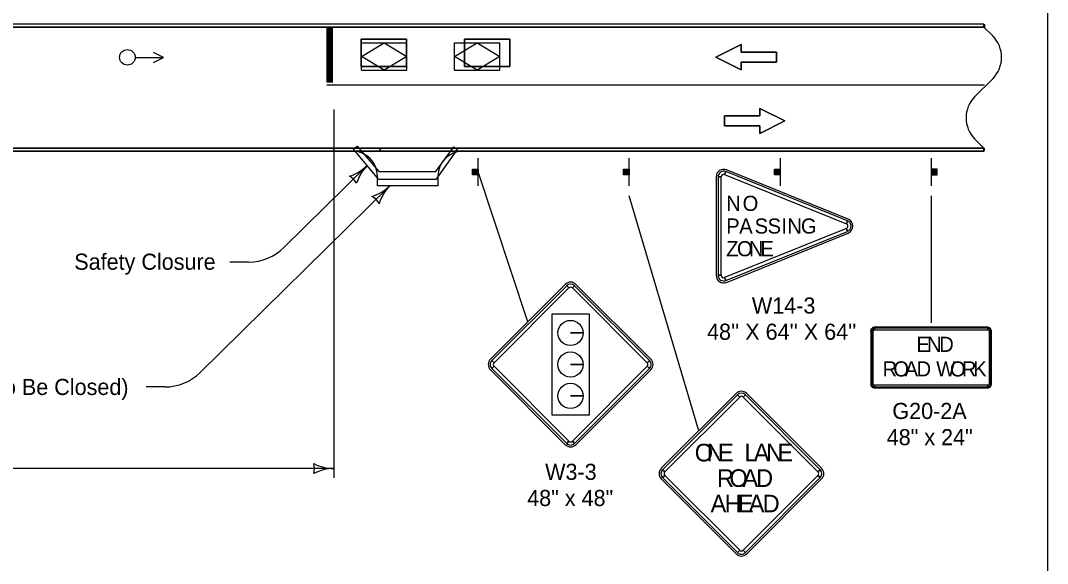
# Model space of a CAD drawing. Extents: x -2134934 to -2119606, y -2139046 to -2137036.
# Drawn here: x -2128116 to -2127097, y -2138077 to -2137539 of the extents above; entities that cross this region are included whole.
import ezdxf

# ---------------------------------------------------------------- set-up
doc = ezdxf.new("R2010")
doc.units = 0
for name, color, linetype in [('Default', 7, 'Continuous'), ('dsnCellElements', 7, 'Continuous'), ('dsnStdLabel', 7, 'Continuous'), ('dsnStdLineWork', 7, 'Continuous'), ('Level 2', 7, 'Continuous'), ('Level 4', 7, 'Continuous')]:
    doc.layers.add(name, color=color, linetype=linetype)

msp = doc.modelspace()

# ---------------------------------------------------------------- linework, layer by layer
at = {"layer": 'Default'}
for p, q in [((-2127785.6, -2137666.4), (-2127781.9, -2137663.4)), ((-2127760.4, -2137696.5), (-2127785.6, -2137666.4)), ((-2127781.9, -2137663.4), (-2127760.4, -2137688.4)), ((-2127704, -2137688.4), (-2127686.2, -2137664.1)), ((-2127682.7, -2137666.7), (-2127704, -2137696.5)), ((-2127686.2, -2137664.1), (-2127682.7, -2137666.7)), ((-2127760.4, -2137688.4), (-2127704, -2137688.4)), ((-2127704, -2137696.5), (-2127760.4, -2137696.5))]:
    msp.add_line(p, q, dxfattribs=at)
msp.add_lwpolyline([(-2130232, -2137035.9), (-2127097, -2137035.9), (-2127097, -2139045.9), (-2130232, -2139045.9)], close=True, dxfattribs=at)
at = {"layer": 'dsnCellElements'}
for centre, radius, start, end in [((-2127802.3, -2137652.6), 42.5, 287.1972, 315.2696), ((-2127741.9, -2137712.4), 42.5, 135.2696, 163.3421), ((-2127797.2, -2137707.8), 16.4, 27.5363, 63.003), ((-2127779.9, -2137672.7), 42.5, 287.1972, 315.2696), ((-2127719.5, -2137732.6), 42.5, 135.2696, 163.3421), ((-2127774.8, -2137728), 16.4, 27.5363, 63.003), ((-2127840.8, -2137983.3), 16.4, 342.2666, 17.7334), ((-2127805.1, -2137940.8), 42.5, 241.9275, 270), ((-2127805.1, -2138025.8), 42.5, 90, 118.0725)]:
    msp.add_arc(centre, radius, start, end, dxfattribs=at)
at = {"layer": 'dsnStdLabel'}
for p, q in [((-2127425.8, -2137693.8), (-2127425.8, -2137791.5)), ((-2127423.9, -2137693.8), (-2127420.8, -2137693.8)), ((-2127417.4, -2137691.5), (-2127416.2, -2137688.6)), ((-2127294.7, -2137735.7), (-2127415.5, -2137686.8)), ((-2127295.4, -2137737.4), (-2127296.5, -2137740.3)), ((-2127415.5, -2137798.5), (-2127294.7, -2137749.6)), ((-2127296.5, -2137745), (-2127295.4, -2137747.9)), ((-2127420.8, -2137791.5), (-2127423.9, -2137791.5)), ((-2127416.2, -2137796.7), (-2127417.4, -2137793.8)), ((-2127575.5, -2137800.5), (-2127649.7, -2137874.7)), ((-2127574.1, -2137801.8), (-2127571.9, -2137804)), ((-2127568.4, -2137804), (-2127566.2, -2137801.8)), ((-2127490.6, -2137874.7), (-2127564.9, -2137800.5)), ((-2127156.2, -2137843.1), (-2127268.7, -2137843.1)), ((-2127268.7, -2137845.6), (-2127268.7, -2137844.1)), ((-2127156.2, -2137844.1), (-2127156.2, -2137845.6)), ((-2127557.8, -2137848.7), (-2127570.3, -2137848.7)), ((-2127570.3, -2137848.7), (-2127557.8, -2137848.7)), ((-2127272.4, -2137846.9), (-2127272.4, -2137899.4)), ((-2127271.5, -2137846.9), (-2127269.9, -2137846.9)), ((-2127154.9, -2137846.9), (-2127153.4, -2137846.9)), ((-2127152.4, -2137899.4), (-2127152.4, -2137846.9)), ((-2127646.2, -2137878.3), (-2127648.4, -2137876.1)), ((-2127491.9, -2137876.1), (-2127494.1, -2137878.3)), ((-2127649.7, -2137885.4), (-2127575.5, -2137959.6)), ((-2127648.4, -2137884), (-2127646.2, -2137881.8)), ((-2127557.8, -2137880), (-2127570.3, -2137880)), ((-2127570.3, -2137880), (-2127557.8, -2137880)), ((-2127564.9, -2137959.6), (-2127490.6, -2137885.4)), ((-2127494.1, -2137881.8), (-2127491.9, -2137884)), ((-2127269.9, -2137899.4), (-2127271.5, -2137899.4)), ((-2127268.7, -2137902.2), (-2127268.7, -2137900.6)), ((-2127268.7, -2137903.1), (-2127156.2, -2137903.1)), ((-2127156.2, -2137900.6), (-2127156.2, -2137902.2)), ((-2127153.4, -2137899.4), (-2127154.9, -2137899.4)), ((-2127557.8, -2137911.2), (-2127570.3, -2137911.2)), ((-2127570.3, -2137911.2), (-2127557.8, -2137911.2)), ((-2127406, -2137908.8), (-2127480.2, -2137983)), ((-2127404.7, -2137910.1), (-2127402.4, -2137912.3)), ((-2127398.9, -2137912.3), (-2127396.7, -2137910.1)), ((-2127321.1, -2137983), (-2127395.4, -2137908.8)), ((-2127571.9, -2137956.1), (-2127574.1, -2137958.3)), ((-2127566.2, -2137958.3), (-2127568.4, -2137956.1)), ((-2127476.7, -2137986.6), (-2127478.9, -2137984.4)), ((-2127322.5, -2137984.4), (-2127324.7, -2137986.6)), ((-2127480.2, -2137993.6), (-2127406, -2138067.9)), ((-2127478.9, -2137992.3), (-2127476.7, -2137990.1)), ((-2127395.4, -2138067.9), (-2127321.1, -2137993.6)), ((-2127324.7, -2137990.1), (-2127322.5, -2137992.3)), ((-2127402.4, -2138064.4), (-2127404.7, -2138066.6)), ((-2127396.7, -2138066.6), (-2127398.9, -2138064.4))]:
    msp.add_line(p, q, dxfattribs=at)
for points in [[(-2127423.9, -2137693.8), (-2127423.9, -2137791.5), (-2127420.8, -2137791.5), (-2127420.8, -2137693.8), (-2127423.9, -2137693.8)], [(-2127295.4, -2137737.4), (-2127416.2, -2137688.6), (-2127417.4, -2137691.5), (-2127296.5, -2137740.3), (-2127295.4, -2137737.4)], [(-2127416.2, -2137796.7), (-2127295.4, -2137747.9), (-2127296.5, -2137745), (-2127417.4, -2137793.8), (-2127416.2, -2137796.7)], [(-2127574.1, -2137801.8), (-2127648.4, -2137876.1), (-2127646.2, -2137878.3), (-2127571.9, -2137804), (-2127574.1, -2137801.8)], [(-2127491.9, -2137876.1), (-2127566.2, -2137801.8), (-2127568.4, -2137804), (-2127494.1, -2137878.3), (-2127491.9, -2137876.1)], [(-2127551.4, -2137830.1), (-2127588.9, -2137830.1), (-2127588.9, -2137930), (-2127551.4, -2137930), (-2127551.4, -2137830.1)], [(-2127156.2, -2137844.1), (-2127268.7, -2137844.1), (-2127268.7, -2137845.6), (-2127156.2, -2137845.6), (-2127156.2, -2137844.1)], [(-2127271.5, -2137846.9), (-2127271.5, -2137899.4), (-2127269.9, -2137899.4), (-2127269.9, -2137846.9), (-2127271.5, -2137846.9)], [(-2127153.4, -2137899.4), (-2127153.4, -2137846.9), (-2127154.9, -2137846.9), (-2127154.9, -2137899.4), (-2127153.4, -2137899.4)], [(-2127648.4, -2137884), (-2127574.1, -2137958.3), (-2127571.9, -2137956.1), (-2127646.2, -2137881.8), (-2127648.4, -2137884)], [(-2127566.2, -2137958.3), (-2127491.9, -2137884), (-2127494.1, -2137881.8), (-2127568.4, -2137956.1), (-2127566.2, -2137958.3)], [(-2127268.7, -2137902.2), (-2127156.2, -2137902.2), (-2127156.2, -2137900.6), (-2127268.7, -2137900.6), (-2127268.7, -2137902.2)], [(-2127404.7, -2137910.1), (-2127478.9, -2137984.4), (-2127476.7, -2137986.6), (-2127402.4, -2137912.3), (-2127404.7, -2137910.1)], [(-2127322.5, -2137984.4), (-2127396.7, -2137910.1), (-2127398.9, -2137912.3), (-2127324.7, -2137986.6), (-2127322.5, -2137984.4)], [(-2127478.9, -2137992.3), (-2127404.7, -2138066.6), (-2127402.4, -2138064.4), (-2127476.7, -2137990.1), (-2127478.9, -2137992.3)], [(-2127396.7, -2138066.6), (-2127322.5, -2137992.3), (-2127324.7, -2137990.1), (-2127398.9, -2138064.4), (-2127396.7, -2138066.6)]]:
    msp.add_lwpolyline(points, close=True, dxfattribs=at)
for centre in [(-2127570.3, -2137848.7), (-2127570.3, -2137880), (-2127570.3, -2137911.2)]:
    msp.add_circle(centre, 12.5, dxfattribs=at)
for centre, radius, start, end in [((-2127418.3, -2137693.8), 7.5, 67.9757, 179.9998), ((-2127418.3, -2137693.8), 5.62, 67.9757, 179.9998), ((-2127418.3, -2137693.8), 2.5, 67.9757, 179.9998), ((-2127297.5, -2137742.6), 2.5, 292.0246, 67.9754), ((-2127297.5, -2137742.6), 5.62, 292.0246, 67.9754), ((-2127297.5, -2137742.6), 7.5, 292.0246, 67.976), ((-2127418.3, -2137791.5), 7.5, 179.9998, 292.0246), ((-2127418.3, -2137791.5), 5.62, 179.9998, 292.0246), ((-2127418.3, -2137791.5), 2.5, 179.9998, 292.0246), ((-2127570.2, -2137805.8), 7.5, 45, 134.9997), ((-2127570.2, -2137805.8), 5.62, 45, 134.9997), ((-2127570.2, -2137805.8), 2.5, 45, 134.9997), ((-2127268.7, -2137846.9), 3.75, 90.0002, 179.9998), ((-2127268.7, -2137846.9), 2.81, 90.0002, 179.9998), ((-2127268.7, -2137846.9), 1.25, 90.0002, 179.9998), ((-2127156.2, -2137846.9), 3.75, 0, 90.0002), ((-2127156.2, -2137846.9), 2.81, 0, 90.0002), ((-2127156.2, -2137846.9), 1.25, 0, 90.0002), ((-2127644.4, -2137880), 7.5, 134.9997, 225), ((-2127644.4, -2137880), 5.62, 134.9997, 225), ((-2127495.9, -2137880), 5.62, 315.0002, 44.9998), ((-2127495.9, -2137880), 7.5, 315.0002, 44.9998), ((-2127644.4, -2137880), 2.5, 134.9997, 225), ((-2127495.9, -2137880), 2.5, 315.0002, 44.9998), ((-2127400.7, -2137914.1), 7.5, 45, 134.9997), ((-2127268.7, -2137899.4), 3.75, 179.9998, 270.0001), ((-2127268.7, -2137899.4), 2.81, 179.9998, 270.0001), ((-2127268.7, -2137899.4), 1.25, 179.9998, 270.0001), ((-2127156.2, -2137899.4), 3.75, 270.0001, 0.0003), ((-2127156.2, -2137899.4), 2.81, 270.0001, 0.0003), ((-2127156.2, -2137899.4), 1.25, 270.0001, 0.0003), ((-2127400.7, -2137914.1), 5.62, 45, 134.9997), ((-2127400.7, -2137914.1), 2.5, 45, 134.9997), ((-2127570.2, -2137954.3), 5.62, 225, 315.0002), ((-2127570.2, -2137954.3), 2.5, 225, 315.0002), ((-2127570.2, -2137954.3), 7.5, 225, 315.0002), ((-2127474.9, -2137988.3), 7.5, 134.9997, 225), ((-2127474.9, -2137988.3), 5.62, 134.9997, 225), ((-2127474.9, -2137988.3), 2.5, 134.9997, 225), ((-2127326.4, -2137988.3), 2.5, 315.0002, 44.9998), ((-2127326.4, -2137988.3), 5.62, 315.0002, 44.9998), ((-2127326.4, -2137988.3), 7.5, 315.0002, 44.9998), ((-2127400.7, -2138062.6), 7.5, 225, 315.0002), ((-2127400.7, -2138062.6), 5.62, 225, 315.0002), ((-2127400.7, -2138062.6), 2.5, 225, 315.0002)]:
    msp.add_arc(centre, radius, start, end, dxfattribs=at)
at = {"layer": 'dsnStdLineWork'}
for p, q in [((-2127160.1, -2137542.2), (-2128660.1, -2137542.2)), ((-2127160.1, -2137542.2), (-2128660.1, -2137542.2)), ((-2127160.1, -2137545.2), (-2128660.1, -2137545.2)), ((-2128660.1, -2137545.2), (-2127810.1, -2137545.2)), ((-2127808.1, -2137545.2), (-2127807.1, -2137545.2)), ((-2127807.1, -2137545.2), (-2127806.1, -2137545.2)), ((-2127806.1, -2137545.2), (-2127805.1, -2137545.2)), ((-2127805.1, -2137545.2), (-2127160.1, -2137545.2)), ((-2127160.1, -2137545.2), (-2127160.1, -2137542.2)), ((-2127159.5, -2137542.2), (-2127159.5, -2137545.2)), ((-2127159.5, -2137602.7), (-2127812, -2137602.7)), ((-2128660.1, -2137665.2), (-2127159.5, -2137665.2)), ((-2127805.1, -2137665.2), (-2128280.3, -2137665.2)), ((-2128278.1, -2137668.2), (-2127805.1, -2137668.2)), ((-2127805.1, -2137668.2), (-2127805.1, -2137665.2)), ((-2127805.1, -2137665.2), (-2127805.1, -2137668.2)), ((-2127758.7, -2137665.2), (-2127805.1, -2137665.2)), ((-2127805.1, -2137668.2), (-2127759.9, -2137668.2)), ((-2127759.9, -2137668.2), (-2127758.7, -2137665.2)), ((-2127758.7, -2137665.2), (-2127759.9, -2137668.2)), ((-2127759.9, -2137668.2), (-2127160.1, -2137668.2)), ((-2127160.1, -2137665.2), (-2127758.7, -2137665.2)), ((-2127160.1, -2137668.2), (-2127160.1, -2137665.2)), ((-2127159.5, -2137668.2), (-2127159.5, -2137665.2))]:
    msp.add_line(p, q, dxfattribs=at)
for points in [[(-2128471.3, -2137545.2), (-2127158.8, -2137545.2)], [(-2127810.1, -2137545.2), (-2127809.1, -2137545.2), (-2127808.1, -2137545.2)], [(-2127160.1, -2137665.2), (-2128470.1, -2137665.2)], [(-2127160.1, -2137668.2), (-2128470.1, -2137668.2)]]:
    msp.add_lwpolyline(points, dxfattribs=at)
at = {"layer": 'Level 2'}
for p, q in [((-2127160.1, -2137545.2), (-2128660.1, -2137545.2)), ((-2127812, -2137545.2), (-2127812, -2137600.2)), ((-2127811, -2137545.2), (-2127811, -2137600.2)), ((-2127810, -2137545.2), (-2127810, -2137600.2)), ((-2127809, -2137545.2), (-2127809, -2137600.2)), ((-2127808, -2137545.2), (-2127808, -2137600.2)), ((-2127807, -2137545.2), (-2127807, -2137600.2)), ((-2127160.1, -2137545.2), (-2127151.3, -2137553.9)), ((-2127151.3, -2137553.9), (-2127160.1, -2137545.2)), ((-2127778.1, -2137557.2), (-2127733.1, -2137557.2)), ((-2127778.1, -2137584.2), (-2127778.1, -2137557.2)), ((-2127733.1, -2137557.2), (-2127778.1, -2137557.2)), ((-2127778.1, -2137557.2), (-2127778.1, -2137584.2)), ((-2127777.8, -2137587.8), (-2127777.8, -2137560.8)), ((-2127777.8, -2137560.8), (-2127732.8, -2137560.8)), ((-2127733.1, -2137557.2), (-2127733.1, -2137584.2)), ((-2127733.1, -2137584.2), (-2127733.1, -2137557.2)), ((-2127732.8, -2137587.8), (-2127732.8, -2137560.8)), ((-2127685.6, -2137587.9), (-2127685.6, -2137560.9)), ((-2127685.6, -2137560.9), (-2127640.6, -2137560.9)), ((-2127675.4, -2137557.2), (-2127630.4, -2137557.2)), ((-2127675.4, -2137584.2), (-2127675.4, -2137557.2)), ((-2127630.4, -2137557.2), (-2127675.4, -2137557.2)), ((-2127675.4, -2137557.2), (-2127675.4, -2137584.2)), ((-2127640.6, -2137587.9), (-2127640.6, -2137560.9)), ((-2127630.4, -2137557.2), (-2127630.4, -2137584.2)), ((-2127630.4, -2137584.2), (-2127630.4, -2137557.2)), ((-2128002.4, -2137575.5), (-2127974.4, -2137575.5)), ((-2127733.1, -2137584.2), (-2127778.1, -2137584.2)), ((-2127778.1, -2137584.2), (-2127733.1, -2137584.2)), ((-2127777.8, -2137587.8), (-2127732.8, -2137587.8)), ((-2127685.6, -2137587.9), (-2127640.6, -2137587.9)), ((-2127630.4, -2137584.2), (-2127675.4, -2137584.2)), ((-2127675.4, -2137584.2), (-2127630.4, -2137584.2)), ((-2127151.3, -2137596.4), (-2127168.9, -2137613.9)), ((-2127168.9, -2137613.9), (-2127151.3, -2137596.4)), ((-2127805.1, -2137627.1), (-2127805.1, -2137992.6)), ((-2127168.9, -2137656.4), (-2127160.1, -2137665.2)), ((-2127160.1, -2137665.2), (-2127168.9, -2137656.4)), ((-2128470.1, -2137665.2), (-2127160.1, -2137665.2)), ((-2127786.9, -2137668.2), (-2127676.9, -2137668.2)), ((-2127854.7, -2137763.9), (-2127772.1, -2137682.5)), ((-2127662, -2137702.7), (-2127662, -2137675.2)), ((-2127512, -2137702.7), (-2127512, -2137675.2)), ((-2127362, -2137702.7), (-2127362, -2137675.2)), ((-2127212.1, -2137702.7), (-2127212.1, -2137675.2)), ((-2127667.3, -2137691.8), (-2127667.3, -2137686.2)), ((-2127667, -2137686.2), (-2127667, -2137691.8)), ((-2127666.7, -2137691.8), (-2127666.7, -2137686.2)), ((-2127666.4, -2137686.2), (-2127666.4, -2137691.8)), ((-2127666.2, -2137691.8), (-2127666.2, -2137686.2)), ((-2127665.8, -2137686.2), (-2127665.8, -2137691.8)), ((-2127665.6, -2137691.8), (-2127665.6, -2137686.2)), ((-2127665.1, -2137686.2), (-2127665.1, -2137691.8)), ((-2127664.8, -2137691.8), (-2127664.8, -2137686.2)), ((-2127664.4, -2137686.2), (-2127664.4, -2137691.8)), ((-2127664.2, -2137691.8), (-2127664.2, -2137686.2)), ((-2127663.9, -2137686.2), (-2127663.9, -2137691.8)), ((-2127663.6, -2137691.8), (-2127663.6, -2137686.2)), ((-2127663.4, -2137686.2), (-2127663.4, -2137691.8)), ((-2127663.2, -2137691.8), (-2127663.2, -2137686.2)), ((-2127662.9, -2137686.2), (-2127662.9, -2137691.8)), ((-2127662.7, -2137691.8), (-2127662.7, -2137686.2)), ((-2127662.4, -2137686.2), (-2127662.4, -2137691.8)), ((-2127612.6, -2137837.6), (-2127662, -2137688.9)), ((-2127517.3, -2137691.8), (-2127517.3, -2137686.2)), ((-2127517, -2137686.2), (-2127517, -2137691.8)), ((-2127516.7, -2137691.8), (-2127516.7, -2137686.2)), ((-2127516.4, -2137686.2), (-2127516.4, -2137691.8)), ((-2127516.2, -2137691.8), (-2127516.2, -2137686.2)), ((-2127515.8, -2137686.2), (-2127515.8, -2137691.8)), ((-2127515.6, -2137691.8), (-2127515.6, -2137686.2)), ((-2127515.1, -2137686.2), (-2127515.1, -2137691.8)), ((-2127514.8, -2137691.8), (-2127514.8, -2137686.2)), ((-2127514.4, -2137686.2), (-2127514.4, -2137691.8)), ((-2127514.2, -2137691.8), (-2127514.2, -2137686.2)), ((-2127513.9, -2137686.2), (-2127513.9, -2137691.8)), ((-2127513.6, -2137691.8), (-2127513.6, -2137686.2)), ((-2127513.4, -2137686.2), (-2127513.4, -2137691.8)), ((-2127513.2, -2137691.8), (-2127513.2, -2137686.2)), ((-2127512.9, -2137686.2), (-2127512.9, -2137691.8)), ((-2127512.7, -2137691.8), (-2127512.7, -2137686.2)), ((-2127512.4, -2137686.2), (-2127512.4, -2137691.8)), ((-2127367.3, -2137691.8), (-2127367.3, -2137686.2)), ((-2127367, -2137686.2), (-2127367, -2137691.8)), ((-2127366.7, -2137691.8), (-2127366.7, -2137686.2)), ((-2127366.4, -2137686.2), (-2127366.4, -2137691.8)), ((-2127366.2, -2137691.8), (-2127366.2, -2137686.2)), ((-2127365.8, -2137686.2), (-2127365.8, -2137691.8)), ((-2127365.6, -2137691.8), (-2127365.6, -2137686.2)), ((-2127365.1, -2137686.2), (-2127365.1, -2137691.8)), ((-2127364.8, -2137691.8), (-2127364.8, -2137686.2)), ((-2127364.4, -2137686.2), (-2127364.4, -2137691.8)), ((-2127364.2, -2137691.8), (-2127364.2, -2137686.2)), ((-2127363.9, -2137686.2), (-2127363.9, -2137691.8)), ((-2127363.6, -2137691.8), (-2127363.6, -2137686.2)), ((-2127363.4, -2137686.2), (-2127363.4, -2137691.8)), ((-2127363.2, -2137691.8), (-2127363.2, -2137686.2)), ((-2127362.9, -2137686.2), (-2127362.9, -2137691.8)), ((-2127362.7, -2137691.8), (-2127362.7, -2137686.2)), ((-2127362.4, -2137686.2), (-2127362.4, -2137691.8)), ((-2127211.7, -2137686.2), (-2127211.7, -2137691.8)), ((-2127211.5, -2137691.8), (-2127211.5, -2137686.2)), ((-2127211.2, -2137686.2), (-2127211.2, -2137691.8)), ((-2127210.9, -2137691.8), (-2127210.9, -2137686.2)), ((-2127210.7, -2137686.2), (-2127210.7, -2137691.8)), ((-2127210.5, -2137691.8), (-2127210.5, -2137686.2)), ((-2127210.2, -2137686.2), (-2127210.2, -2137691.8)), ((-2127209.9, -2137691.8), (-2127209.9, -2137686.2)), ((-2127209.7, -2137686.2), (-2127209.7, -2137691.8)), ((-2127209.4, -2137691.8), (-2127209.4, -2137686.2)), ((-2127209, -2137686.2), (-2127209, -2137691.8)), ((-2127208.5, -2137691.8), (-2127208.5, -2137686.2)), ((-2127208.3, -2137686.2), (-2127208.3, -2137691.8)), ((-2127207.9, -2137691.8), (-2127207.9, -2137686.2)), ((-2127207.7, -2137686.2), (-2127207.7, -2137691.8)), ((-2127207.4, -2137691.8), (-2127207.4, -2137686.2)), ((-2127207.1, -2137686.2), (-2127207.1, -2137691.8)), ((-2127206.8, -2137691.8), (-2127206.8, -2137686.2)), ((-2127937.8, -2137887.9), (-2127749.7, -2137702.6)), ((-2127443.1, -2137945.9), (-2127512, -2137712.7)), ((-2127212, -2137838.7), (-2127212, -2137712.7)), ((-2127889.8, -2137778.3), (-2127908.3, -2137778.3)), ((-2127972.9, -2137902.3), (-2127991.4, -2137902.3)), ((-2127805.1, -2137983.3), (-2128464.5, -2137983.3))]:
    msp.add_line(p, q, dxfattribs=at)
for points in [[(-2127984.1, -2137580.3), (-2127974.1, -2137575.3), (-2127984.1, -2137570.3)], [(-2127401, -2137580), (-2127401, -2137587.5), (-2127426, -2137575), (-2127401, -2137562.5), (-2127401, -2137570), (-2127366, -2137570), (-2127366, -2137580), (-2127401, -2137580)], [(-2127382.5, -2137633.3), (-2127382.5, -2137625.8), (-2127357.5, -2137638.3), (-2127382.5, -2137650.8), (-2127382.5, -2137643.3), (-2127417.5, -2137643.3), (-2127417.5, -2137633.3), (-2127382.5, -2137633.3)], [(-2127701.9, -2137693.2), (-2127701.9, -2137702.6), (-2127761.9, -2137702.6), (-2127761.9, -2137693.2)]]:
    msp.add_lwpolyline(points, dxfattribs=at)
for points in [[(-2127366, -2137580), (-2127366, -2137570), (-2127401, -2137570), (-2127401, -2137562.5), (-2127426, -2137575), (-2127401, -2137587.5), (-2127401, -2137580)], [(-2127417.5, -2137633.3), (-2127417.5, -2137643.3), (-2127382.5, -2137643.3), (-2127382.5, -2137650.8), (-2127357.5, -2137638.3), (-2127382.5, -2137625.8), (-2127382.5, -2137633.3)], [(-2127662.1, -2137686.2), (-2127662.1, -2137691.8), (-2127667.7, -2137691.8), (-2127667.7, -2137686.2)], [(-2127512.1, -2137686.2), (-2127512.1, -2137691.8), (-2127517.7, -2137691.8), (-2127517.7, -2137686.2)], [(-2127362.1, -2137686.2), (-2127362.1, -2137691.8), (-2127367.7, -2137691.8), (-2127367.7, -2137686.2)], [(-2127212.1, -2137686.2), (-2127212.1, -2137691.8), (-2127206.4, -2137691.8), (-2127206.4, -2137686.2)]]:
    msp.add_lwpolyline(points, close=True, dxfattribs=at)
msp.add_circle((-2128010.1, -2137575.2), 7.74, dxfattribs=at)
for centre, radius, start, end in [((-2127172.5, -2137575.2), 30, 315, 45), ((-2127172.5, -2137575.2), 30, 315, 45), ((-2127147.7, -2137635.2), 30, 135, 225), ((-2127147.7, -2137635.2), 30, 135, 225), ((-2127786.9, -2137693.2), 25, 0, 90), ((-2127676.9, -2137693.2), 25, 90, 180), ((-2127889.8, -2137728.3), 50, 270, 314.5635), ((-2127972.9, -2137852.3), 50, 270, 314.5635)]:
    msp.add_arc(centre, radius, start, end, dxfattribs=at)
at = {"layer": 'Level 4'}
for points in [[(-2127777.8, -2137574.3), (-2127755.3, -2137560.8), (-2127732.8, -2137574.3), (-2127755.3, -2137587.8)], [(-2127685.6, -2137574.4), (-2127663.1, -2137560.9), (-2127640.6, -2137574.4), (-2127663.1, -2137587.9)]]:
    msp.add_lwpolyline(points, close=True, dxfattribs=at)

# ---------------------------------------------------------------- texts
at = {"layer": 'dsnStdLabel'}
for s, height, p in [('N', 15, (-2127415.8, -2137727.6)), ('O', 15, (-2127399.5, -2137727.6)), ('P', 15, (-2127415.8, -2137750.1)), ('A', 15, (-2127402.9, -2137750.1)), ('S', 15, (-2127387.6, -2137750.1)), ('S', 15, (-2127374.7, -2137750.1)), ('I', 15, (-2127361.1, -2137750.1)), ('N', 15, (-2127355.2, -2137750.1)), ('G', 15, (-2127341.6, -2137750.1)), ('Z', 15, (-2127415.8, -2137772.6)), ('O', 15, (-2127405.1, -2137772.6)), ('N', 15, (-2127393.3, -2137772.6)), ('E', 15, (-2127381.9, -2137772.6)), ('W14-3', 16, (-2127390.3, -2137829.5)), ("48'' X 64'' X 64''", 16, (-2127434.8, -2137855.5)), ('E', 15, (-2127227.1, -2137867.5)), ('N', 15, (-2127216.5, -2137867.5)), ('D', 15, (-2127204.4, -2137867.5)), ('R', 15, (-2127260.6, -2137891.9)), ('O', 15, (-2127249.9, -2137891.9)), ('A', 15, (-2127238.7, -2137891.9)), ('D', 15, (-2127226.9, -2137891.9)), ('W', 15, (-2127207.4, -2137891.9)), ('O', 15, (-2127193.7, -2137891.9)), ('R', 15, (-2127181.9, -2137891.9)), ('K', 15, (-2127170.6, -2137891.9)), ('G20-2A', 16, (-2127250.9, -2137934.1)), ('48" x 24"', 16, (-2127256.5, -2137960.1)), ('O', 17.5, (-2127447, -2137976.2)), ('N', 17.5, (-2127435.2, -2137976.2)), ('E', 17.5, (-2127424, -2137976.2)), ('L', 17.5, (-2127397.7, -2137976.2)), ('A', 17.5, (-2127388.5, -2137976.2)), ('N', 17.5, (-2127376.2, -2137976.2)), ('E', 17.5, (-2127365, -2137976.2)), ('W3-3', 16, (-2127595.5, -2137994.5)), ('R', 17.5, (-2127424.9, -2138001.5)), ('O', 17.5, (-2127412.6, -2138001.5)), ('A', 17.5, (-2127399.7, -2138001.5)), ('D', 17.5, (-2127386.1, -2138001.5)), ('48" x 48"', 16, (-2127613.3, -2138020.5)), ('A', 17.5, (-2127431.3, -2138026.8)), ('H', 17.5, (-2127417.4, -2138026.8)), ('E', 17.5, (-2127404.2, -2138026.8)), ('A', 17.5, (-2127393.5, -2138026.8)), ('D', 17.5, (-2127379.6, -2138026.8))]:
    msp.add_text(s, height=height, dxfattribs=at).set_placement(p)
at = {"layer": 'Level 2'}
for s, p in [('Safety Closure', (-2128062.8, -2137786)), ('265th Road (To Be Closed)', (-2128269.4, -2137910.3))]:
    msp.add_text(s, height=16, dxfattribs=at).set_placement(p)

doc.saveas('drawing.dxf')
